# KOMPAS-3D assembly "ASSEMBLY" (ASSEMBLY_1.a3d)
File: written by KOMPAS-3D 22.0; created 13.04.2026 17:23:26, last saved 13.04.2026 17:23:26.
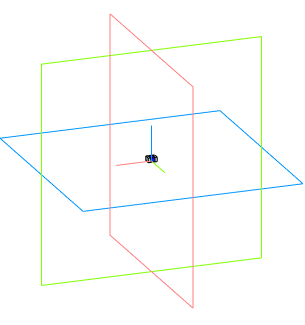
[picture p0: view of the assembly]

Document properties: Автор: Andrey; Полное имя файла: C:\Users\User1\Documents\ASSEMBLY_1.a3d

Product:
- Component [detail]: term1  | qty 1  | source file: term1.m3d
- Component [detail]: term2  | qty 1  | source file: term2.m3d
- Component [detail]: body  | qty 1  | source file: body_2.m3d
- Part/product: ASSEMBLY

Referenced files in C:\Users\User1\Documents\: term1.m3d, term2.m3d, body_2.m3d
